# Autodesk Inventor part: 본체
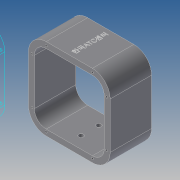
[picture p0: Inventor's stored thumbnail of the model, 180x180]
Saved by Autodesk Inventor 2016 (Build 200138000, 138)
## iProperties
Created: 2016-12
Part Number: 본체
Material: 알루미늄 6061
Document SubType Name: Modeling
Designer: mduedu
Density: 2.71 g/cm^3
Mass: 883.341 g
Surface Area: 772.714 cm^2
Volume: 325.956 cm^3
Appearance: 기본값
Author: mduedu
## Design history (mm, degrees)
sketch "스케치1"
  geometry: L1 (-46, 42)-(-46, -36); L2 (-16, 72)-(62, 72); L3 (92, 42)-(92, -36); L4 (62, -66)-(-16, -66); A1 r 30 centre (-16, -36) between (-46, -36) and (-16, -66); A2 r 30 centre (62, 42) between (92, 42) and (62, 72); A3 r 30 centre (62, -36) between (62, -66) and (92, -36); A4 r 30 centre (-16, 42) between (-16, 72) and (-46, 42); 1 further point
  constraints: 8 end point, 8 point on circle, 8 tangent, 4 centre point, 3 equal radius, 1 horizontal, 1 perpendicular, 1 vertical
  dimensions: "d83" = 30 radius of A2; "d84" = 92 distance from line of L3 point (0, 0); "d85" = 138 distance between parallel lines of L4 L2; "d86" = 46 distance from line of L1 point (0, 0); "d87" = 72 distance from line of point (0, 0) L2
extrude "돌출1" new body sketch "스케치1" stored distance "d3" = 70; taper "d4" = 0 deg
feature "쉘1" dims "d5" = 10
sketch "스케치10"
  geometry: L1 (78, 70)-(0, 70) reference; L2 (-30, 70)-(-30, 0) reference; 4 further points
  constraints: 1 coincident, 1 horizontal alignment, 1 midpoint, 1 vertical alignment, 1 other
  dimensions: "d88" = 35 distance of point (39, 35) point (39, 70) (derived); "d89" = 69 distance from line of point (39, 35) L2 (derived)
feature "엠보싱1" sketch "스케치10" dims "d61" = 0.5, "d62" = 0, "d83" = 30, "d84" = 92, "d85" = 138, "d86" = 46, "d87" = 72
sketch "스케치11"
  geometry: L1 (-36, -36)-(-36, 42) reference; L2 (-16, 62)-(62, 62) reference; L3 (82, 42)-(82, -36) reference; L4 (62, -56)-(-16, -56) reference; L5 (-16, -66)-(62, -66) reference; L6 (92, -36)-(92, 42) reference; L7 (62, 72)-(-16, 72) reference; L8 (-46, 42)-(-46, -36) reference; L9 (-16, 66)-(62, 66); L10 (86, 42)-(86, -36); L11 (62, -60)-(-16, -60); L12 (-40, -36)-(-40, 42); A1 r 20 centre (-16, -36) between (-36, -36) and (-16, -56) reference; A2 r 20 centre (-16, 42) between (-16, 62) and (-36, 42) reference; A3 r 20 centre (62, 42) between (82, 42) and (62, 62) reference; A4 r 20 centre (62, -36) between (62, -56) and (82, -36) reference; A5 r 30 centre (-16, -36) between (-46, -36) and (-16, -66) reference; A6 r 30 centre (62, -36) between (62, -66) and (92, -36) reference; A7 r 30 centre (62, 42) between (92, 42) and (62, 72) reference; A8 r 30 centre (-16, 42) between (-16, 72) and (-46, 42) reference; A9 r 24 centre (62, 42) between (86, 42) and (62, 66); A10 r 24 centre (62, -36) between (62, -60) and (86, -36); A11 r 24 centre (-16, -36) between (-40, -36) and (-16, -60); A12 r 24 centre (-16, 42) between (-16, 66) and (-40, 42); 8 further points
  constraints: 8 coincident, 8 end point, 8 point on circle, 4 centre point, 7 other
  dimensions: "d90" = 6 distance between parallel lines of L9 L7
hole "구멍3" sketch "스케치11" at (-16, 66), (-40, 42), (-40, -36), (-16, -60), (62, -60), (86, -36), (86, 42), (62, 66) diameter "d63" = 3.242; stored, may be unused: countersink angle "d67" = 90 deg, drill point angle "d69" = 120 deg; dims "d64" = 8.6, "d65" = 4, "d66" = 2, "d68" = 10.6
sketch "스케치12"
  geometry: L1 (16, -56)-(-62, -56) reference; L2 (-82, -36)-(-82, 42) reference; L3 (-62, 62)-(16, 62) reference; L4 (36, 42)-(36, -36) reference; L5 (46, -36)-(46, 42) reference; L6 (16, 72)-(-62, 72) reference; L7 (-92, 42)-(-92, -36) reference; L8 (-62, -66)-(16, -66) reference; L9 (-62, 66)-(16, 66); L10 (40, 42)-(40, -36); L11 (16, -60)-(-62, -60); L12 (-86, -36)-(-86, 42); A1 r 20 centre (16, -36) between (16, -56) and (36, -36) reference; A2 r 20 centre (-62, -36) between (-82, -36) and (-62, -56) reference; A3 r 20 centre (-62, 42) between (-62, 62) and (-82, 42) reference; A4 r 20 centre (16, 42) between (36, 42) and (16, 62) reference; A5 r 30 centre (16, -36) between (16, -66) and (46, -36) reference; A6 r 30 centre (16, 42) between (46, 42) and (16, 72) reference; A7 r 30 centre (-62, 42) between (-62, 72) and (-92, 42) reference; A8 r 30 centre (-62, -36) between (-92, -36) and (-62, -66) reference; A9 r 24 centre (16, 42) between (40, 42) and (16, 66); A10 r 24 centre (16, -36) between (16, -60) and (40, -36); A11 r 24 centre (-62, -36) between (-86, -36) and (-62, -60); A12 r 24 centre (-62, 42) between (-62, 66) and (-86, 42); 8 further points
  constraints: 8 coincident, 8 end point, 8 point on circle, 4 centre point, 7 other
  dimensions: "d91" = 6 distance between parallel lines of L9 L6
hole "구멍5" sketch "스케치12" at (-62, 66), (-86, 42), (-86, -36), (-62, -60), (16, -60), (40, -36), (40, 42), (16, 66) diameter "d70" = 3.242; stored, may be unused: countersink angle "d74" = 90 deg, drill point angle "d76" = 120 deg; dims "d71" = 8.6, "d72" = 4, "d73" = 2, "d75" = 10.6
sketch "스케치15"
  geometry: L1 (135.6, -35)-(-57.6, -35) reference; L2 (78, 0)-(0, 0) reference; L3 (0, -70)-(78, -70) reference; L4 (39, 0)-(39, -70); C1 r 4 at (39, -20); C2 r 4 at (39, -50); 1 further point
  constraints: 2 centre point, 2 end point, 2 midpoint, 1 point on line, 1 symmetric about line, 1 other
  dimensions: "d92" = 8 diameter of C1; "d93" = 15 distance from line of C1.centre L1
extrude "돌출6" cut sketch "스케치15" stored distance "d94" = 10; taper "d95" = 0 deg
node "솔리드1"
node "투영된 루프3"
node "투영된 루프4"
